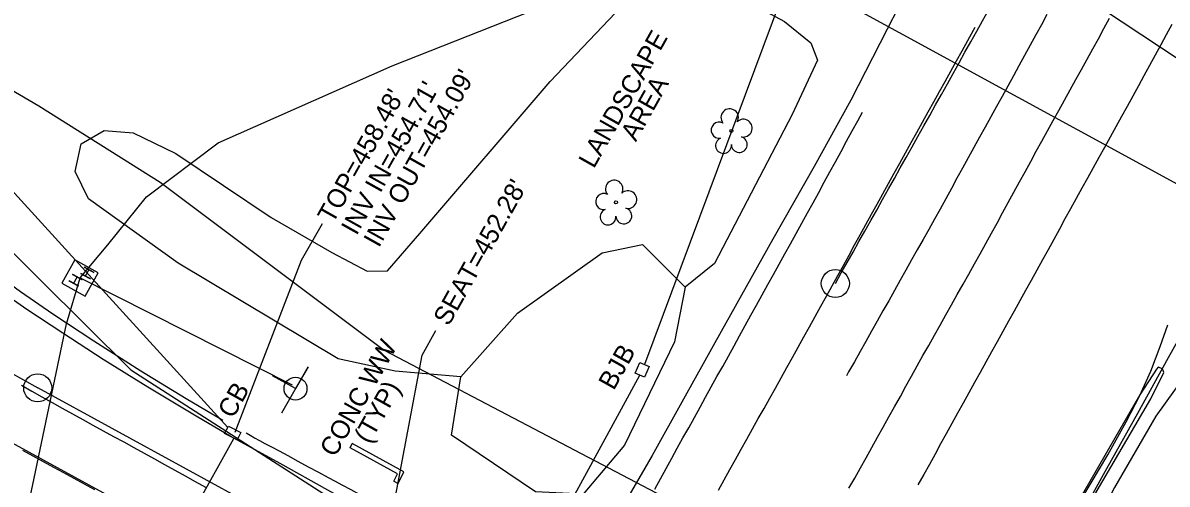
# Model space of a CAD drawing. Extents: x 2074109 to 2077820, y 741079 to 746031.
# Drawn here: x 2075369.9 to 2075614.7, y 743471.4 to 743570.1 of the extents above; entities that cross this region are included whole.
import ezdxf

# ---------------------------------------------------------------- set-up
doc = ezdxf.new("R2010")
doc.units = 0
for name, color, linetype in [('Exist Guardrail', 7, 'Continuous'), ('Exist Horizontal Alignment', 7, 'Continuous'), ('Exist Horizontal Alignment Point', 7, 'Continuous'), ('Exist Roads Curbs', 7, 'Continuous'), ('Exist Roads EOP', 7, 'Continuous'), ('Exist Roads EOT', 7, 'Continuous'), ('Exist Structure Major Bridge Seat Leader', 7, 'Continuous'), ('Exist Structure Major Bridge Seat Top Elevation', 7, 'Continuous'), ('Exist Structure Major Bridge WW Text', 7, 'Continuous'), ('Exist Structure Minor Catch Basin', 7, 'Continuous'), ('Exist Structure Minor Catch Basin Leader', 7, 'Continuous'), ('Exist Structure Minor Catch Basin Text', 7, 'Continuous'), ('Exist Structure Minor Catch Basin Top Elevation', 7, 'Continuous'), ('Exist Structure Minor Head and End Wall', 7, 'Continuous'), ('Exist Structure Minor Junction Box', 7, 'Continuous'), ('Exist Structure Minor Junction Box Text', 7, 'Continuous'), ('Exist Structure Minor Pipes RCP 15 Inch', 7, 'Continuous'), ('Exist Structure Minor Pipes RCP 15 Inch Invert', 7, 'Continuous'), ('Exist Structure Minor Pipes RCP 36 Inch', 7, 'Continuous'), ('Exist Utilities Gas UG Line SUE LOS B', 7, 'Continuous'), ('Exist Utilities Power Joint Use Telephone CELL', 7, 'Continuous'), ('Exist Utilities Power UG Cable SUE LOS B', 7, 'Continuous'), ('Exist Utilities Telephone UG Conduit SUE LOS B', 7, 'Continuous'), ('Exist Utilities Telephone UG FO SUE LOS B', 7, 'Continuous'), ('Exist Utilities TV Hand Hole CELL', 7, 'Continuous'), ('Exist Utilities Water UG Line SUE LOS B', 7, 'Continuous'), ('Exist Vegetation Hedge Row', 7, 'Continuous'), ('Exist Vegetation Hedge Row Text', 7, 'Continuous'), ('Exist Vegetation Tree CELL', 7, 'Continuous'), ('Exist Vegetation Woods Line', 7, 'Continuous')]:
    doc.layers.add(name, color=color, linetype=linetype)

msp = doc.modelspace()

# ---------------------------------------------------------------- linework, layer by layer
at = {"layer": 'Exist Guardrail'}
msp.add_line((2075608.81, 743490.52), (2075585.08, 743449.24), dxfattribs=at)
msp.add_lwpolyline([(2075566.68, 743406.83), (2075570.84, 743414.46), (2075580.6, 743432.36), (2075594.55, 743459.51), (2075599.18, 743469.22), (2075611.18, 743489.67), (2075614, 743495.32), (2075613.66, 743496.05), (2075612.79, 743496.46), (2075612.4, 743496.03), (2075608.81, 743490.52)], dxfattribs=at)
at = {"layer": 'Exist Horizontal Alignment'}
for p, q in [((2074769.18, 743807.11), (2075920.37, 743178.35)), ((2075444.78, 743452.87), (2075373.12, 743492))]:
    msp.add_line(p, q, dxfattribs=at)
for centre, radius, start, end in [((2065746.77, 748969.72), 11283.45, 330.581241, 339.398504), ((2065715.23, 749056.64), 11283.45, 330.581241, 331.000067), ((2075492.33, 743710.26), 248.69, 215.7386, 241.3572)]:
    msp.add_arc(centre, radius, start, end, dxfattribs=at)
at = {"layer": 'Exist Horizontal Alignment Point'}
for centre in [(2075543.71, 743514.33), (2075373.12, 743492)]:
    msp.add_circle(centre, 3, dxfattribs=at)
at = {"layer": 'Exist Roads Curbs'}
for points in [[(2075307.15, 743570.9), (2075310.12, 743567.26), (2075315.37, 743561.06), (2075321.1, 743554.42), (2075325.85, 743549.26), (2075330.36, 743544.77), (2075335.65, 743539.76), (2075345.03, 743531.53), (2075356.37, 743522.33), (2075363.48, 743516.95), (2075369.43, 743512.64), (2075376.35, 743507.87), (2075385.09, 743502.08), (2075395.18, 743495.66), (2075404.84, 743489.75), (2075412, 743485.54), (2075412.72, 743485.12)], [(2075417.69, 743482.38), (2075418.53, 743481.88), (2075419.49, 743481.34), (2075420.55, 743480.75), (2075421.73, 743480.12), (2075423.1, 743479.4), (2075424.73, 743478.52), (2075426.61, 743477.5), (2075428.76, 743476.34), (2075430.99, 743475.12), (2075433.14, 743473.96), (2075435.22, 743472.85), (2075436.72, 743472.05), (2075438.18, 743471.28), (2075440.06, 743470.26), (2075441.88, 743469.26), (2075443.64, 743468.26), (2075444.49, 743467.77)]]:
    msp.add_lwpolyline(points, dxfattribs=at)
at = {"layer": 'Exist Roads EOP'}
for points in [[(2075559.5, 743577.98), (2075554.8, 743568.73), (2075547.03, 743553.55), (2075539.18, 743539.38), (2075530.34, 743523.8), (2075517.96, 743501.62), (2075504.54, 743477.52), (2075492.04, 743456), (2075482.7, 743440.16), (2075465.16, 743408.97), (2075448.94, 743380.02), (2075438.36, 743361.14), (2075432.82, 743350.24), (2075423.13, 743332.91), (2075408.43, 743306.71), (2075394.81, 743282.87), (2075378.9, 743255.03), (2075364.05, 743228.71), (2075347.68, 743199.79), (2075332.2, 743172.4), (2075317.22, 743145.53), (2075301.28, 743116.93)], [(2075445.35, 743464.44), (2075424.96, 743475.81), (2075414.28, 743481.69), (2075407.34, 743485.74), (2075396.65, 743492.12), (2075387.15, 743498.07), (2075378.48, 743503.71), (2075370.8, 743508.8), (2075365.1, 743512.76), (2075359.72, 743516.76), (2075352.43, 743522.45), (2075343.87, 743529.41), (2075336.63, 743535.65), (2075330.1, 743541.75), (2075323.4, 743548.45), (2075316.7, 743555.85), (2075309.06, 743565.08), (2075302.29, 743573.79)], [(2075629.48, 743509.98), (2075612.24, 743485.93), (2075603.42, 743470.69), (2075597.29, 743458.57), (2075588.31, 743442.87), (2075576.16, 743421.96), (2075567.04, 743406.6), (2075558.96, 743392.83), (2075547.09, 743371), (2075533.33, 743345.7), (2075516.25, 743314.4), (2075505.25, 743295.15), (2075496.54, 743281.14), (2075486.37, 743264.69)], [(2075486.59, 743271.21), (2075492.62, 743282.79), (2075498.41, 743293.66), (2075503.35, 743303.11), (2075507.27, 743311), (2075512.55, 743321.1), (2075520.08, 743334.84), (2075528.48, 743350.15), (2075537.18, 743366.11), (2075545.57, 743381.57), (2075553.44, 743396.13), (2075561.87, 743411.12), (2075571.26, 743427.01), (2075580.6, 743442.44), (2075589.42, 743456.78), (2075596.67, 743468.69), (2075601.96, 743477.67), (2075605.92, 743484.73), (2075608.84, 743490.35), (2075611.2, 743495.58), (2075613.21, 743500.83), (2075614.86, 743505.48)]]:
    msp.add_lwpolyline(points, dxfattribs=at)
at = {"layer": 'Exist Roads EOT'}
for points in [[(2075588.98, 743571.9), (2075587.79, 743569.71), (2075586.59, 743567.51), (2075585.4, 743565.32), (2075584.2, 743563.12), (2075582.99, 743560.93), (2075581.79, 743558.74), (2075580.58, 743556.55), (2075579.38, 743554.36), (2075578.17, 743552.17), (2075576.97, 743549.98), (2075575.76, 743547.79), (2075574.55, 743545.61), (2075573.35, 743543.42), (2075572.14, 743541.23), (2075570.94, 743539.04), (2075569.73, 743536.85), (2075568.53, 743534.65), (2075567.33, 743532.46), (2075566.13, 743530.27), (2075564.92, 743528.08), (2075563.69, 743525.9), (2075562.47, 743523.72), (2075561.24, 743521.55), (2075560.02, 743519.37), (2075558.8, 743517.19), (2075557.57, 743515.01), (2075556.35, 743512.83), (2075555.13, 743510.65), (2075553.9, 743508.47), (2075552.68, 743506.29), (2075551.46, 743504.11), (2075550.23, 743501.93), (2075549, 743499.75), (2075547.78, 743497.57), (2075546.55, 743495.4), (2075546.09, 743494.58)], [(2075546.63, 743470.52), (2075547.85, 743472.7), (2075549.07, 743474.88), (2075550.29, 743477.06), (2075551.52, 743479.24), (2075552.74, 743481.43), (2075553.96, 743483.61), (2075555.18, 743485.79), (2075556.4, 743487.97), (2075557.62, 743490.15), (2075558.82, 743492.34), (2075560.03, 743494.53), (2075561.24, 743496.72), (2075562.46, 743498.9), (2075563.68, 743501.08), (2075564.91, 743503.26), (2075566.13, 743505.44), (2075567.35, 743507.62), (2075568.58, 743509.8), (2075569.8, 743511.98), (2075571.02, 743514.16), (2075572.25, 743516.34), (2075573.47, 743518.52), (2075574.69, 743520.7), (2075575.92, 743522.88), (2075577.12, 743525.07), (2075578.31, 743527.27), (2075579.49, 743529.47), (2075580.68, 743531.67), (2075581.88, 743533.86), (2075583.08, 743536.05), (2075584.29, 743538.24), (2075585.49, 743540.43), (2075586.7, 743542.62), (2075587.9, 743544.81), (2075589.11, 743547), (2075590.31, 743549.19), (2075591.51, 743551.38), (2075592.72, 743553.57), (2075593.92, 743555.76), (2075595.13, 743557.96), (2075596.34, 743560.14), (2075597.55, 743562.33), (2075598.77, 743564.51), (2075599.98, 743566.7), (2075601.16, 743568.9), (2075602.34, 743571.1)], [(2075518.73, 743470.13), (2075519.95, 743472.31), (2075521.16, 743474.5), (2075522.38, 743476.68), (2075523.6, 743478.86), (2075524.81, 743481.05), (2075526.03, 743483.23), (2075527.24, 743485.42), (2075528.46, 743487.6), (2075529.68, 743489.78), (2075530.89, 743491.97), (2075532.11, 743494.15), (2075533.32, 743496.34), (2075534.54, 743498.52), (2075535.76, 743500.7), (2075536.97, 743502.89), (2075538.19, 743505.07), (2075539.4, 743507.26), (2075540.6, 743509.45), (2075541.81, 743511.64), (2075543.02, 743513.83), (2075544.22, 743516.02), (2075545.43, 743518.21), (2075546.64, 743520.4), (2075547.84, 743522.58), (2075549.05, 743524.77), (2075550.26, 743526.96), (2075551.46, 743529.15), (2075552.67, 743531.34), (2075553.88, 743533.53), (2075555.08, 743535.72), (2075556.29, 743537.91), (2075557.5, 743540.1), (2075558.71, 743542.28), (2075559.92, 743544.47), (2075561.13, 743546.65), (2075562.35, 743548.84), (2075563.56, 743551.03), (2075564.77, 743553.21), (2075565.99, 743555.4), (2075567.2, 743557.58), (2075568.41, 743559.77), (2075569.63, 743561.95), (2075570.84, 743564.14), (2075572.05, 743566.32), (2075573.27, 743568.51), (2075573.62, 743569.15)], [(2075615.7, 743569.76), (2075614.5, 743567.57), (2075613.31, 743565.37), (2075612.11, 743563.18), (2075610.92, 743560.98), (2075609.72, 743558.78), (2075608.52, 743556.59), (2075607.32, 743554.4), (2075606.11, 743552.21), (2075604.9, 743550.03), (2075603.7, 743547.84), (2075602.49, 743545.65), (2075601.28, 743543.46), (2075600.07, 743541.27), (2075598.87, 743539.08), (2075597.66, 743536.89), (2075596.45, 743534.7), (2075595.25, 743532.51), (2075594.04, 743530.32), (2075592.83, 743528.14), (2075591.63, 743525.95), (2075590.42, 743523.76), (2075589.21, 743521.57), (2075588, 743519.38), (2075586.8, 743517.19), (2075585.59, 743515), (2075584.38, 743512.81), (2075583.18, 743510.62), (2075581.97, 743508.44), (2075580.76, 743506.25), (2075579.55, 743504.06), (2075578.34, 743501.87), (2075577.13, 743499.69), (2075575.92, 743497.5), (2075574.71, 743495.31), (2075573.5, 743493.12), (2075572.29, 743490.94), (2075571.08, 743488.75), (2075569.87, 743486.56), (2075568.66, 743484.37), (2075567.45, 743482.19), (2075566.24, 743480), (2075565.03, 743477.81), (2075563.82, 743475.62), (2075562.61, 743473.44), (2075561.39, 743471.25)], [(2075505.08, 743470.36), (2075506.29, 743472.55), (2075507.5, 743474.74), (2075508.71, 743476.93), (2075509.92, 743479.11), (2075511.13, 743481.3), (2075512.35, 743483.48), (2075513.56, 743485.67), (2075514.77, 743487.86), (2075515.98, 743490.04), (2075517.19, 743492.23), (2075518.4, 743494.42), (2075519.62, 743496.6), (2075520.83, 743498.79), (2075522.04, 743500.98), (2075523.25, 743503.16), (2075524.46, 743505.35), (2075525.67, 743507.54), (2075526.88, 743509.72), (2075528.09, 743511.91), (2075529.3, 743514.1), (2075530.51, 743516.28), (2075531.73, 743518.47), (2075532.94, 743520.66), (2075534.15, 743522.84), (2075535.36, 743525.03), (2075536.56, 743527.22), (2075537.76, 743529.42), (2075538.95, 743531.61), (2075540.15, 743533.81), (2075541.34, 743536), (2075542.54, 743538.2), (2075543.73, 743540.39), (2075544.93, 743542.59), (2075546.12, 743544.78), (2075547.32, 743546.98), (2075548.51, 743549.17), (2075549.51, 743551)], [(2075369.65, 743492.55), (2075371.83, 743491.33), (2075374.01, 743490.11), (2075376.19, 743488.9), (2075378.38, 743487.69), (2075380.57, 743486.47), (2075382.75, 743485.26), (2075384.94, 743484.05), (2075387.13, 743482.84), (2075389.32, 743481.63), (2075391.51, 743480.42), (2075393.69, 743479.21), (2075395.88, 743478.01), (2075398.07, 743476.8), (2075400.26, 743475.59), (2075402.45, 743474.38), (2075404.63, 743473.17), (2075406.82, 743471.96), (2075409.01, 743470.75)], [(2075369.9, 743478.68), (2075372.09, 743477.48), (2075374.28, 743476.27), (2075376.47, 743475.06), (2075378.66, 743473.86), (2075380.86, 743472.66), (2075383.05, 743471.46), (2075385.24, 743470.27)]]:
    msp.add_lwpolyline(points, dxfattribs=at)
at = {"layer": 'Exist Structure Major Bridge Seat Leader'}
msp.add_lwpolyline([(2075449.18, 743466.47), (2075455.35, 743499.03), (2075458.28, 743504.27)], dxfattribs=at)
at = {"layer": 'Exist Structure Minor Catch Basin'}
msp.add_lwpolyline([(2075413.89, 743483.84), (2075416.59, 743482.46), (2075415.78, 743480.87), (2075413.08, 743482.25)], close=True, dxfattribs=at)
at = {"layer": 'Exist Structure Minor Catch Basin Leader'}
msp.add_lwpolyline([(2075415.33, 743482.54), (2075429.57, 743519.34), (2075434, 743527.2)], dxfattribs=at)
at = {"layer": 'Exist Structure Minor Head and End Wall'}
for points in [[(2075449.29, 743472.02), (2075450.1, 743473.63), (2075439.92, 743479.2), (2075440.4, 743480.08)], [(2075449.29, 743472.02), (2075450.18, 743471.57), (2075451.43, 743474.04), (2075440.4, 743480.08)]]:
    msp.add_lwpolyline(points, dxfattribs=at)
at = {"layer": 'Exist Structure Minor Junction Box'}
msp.add_lwpolyline([(2075500.9, 743495.15), (2075501.87, 743497.44), (2075503.9, 743496.58), (2075502.93, 743494.29)], close=True, dxfattribs=at)
at = {"layer": 'Exist Structure Minor Pipes RCP 15 Inch'}
for p, q in [((2075413.76, 743483.52), (2075273.44, 743637.59)), ((2075372.17, 743404.16), (2075415.09, 743481.19))]:
    msp.add_line(p, q, dxfattribs=at)
at = {"layer": 'Exist Structure Minor Pipes RCP 36 Inch'}
for p, q in [((2075597.45, 743750.35), (2075502.89, 743497.01)), ((2075364.8, 743242.78), (2075501.91, 743494.72))]:
    msp.add_line(p, q, dxfattribs=at)
at = {"layer": 'Exist Utilities Gas UG Line SUE LOS B'}
msp.add_lwpolyline([(2075544.69, 743574.93), (2075774.64, 743449.58), (2075786.68, 743440.92), (2075834.72, 743415.6), (2075897.9, 743381.57), (2075936.93, 743360.69), (2075971.28, 743343.48), (2075996.08, 743328.1)], dxfattribs=at)
at = {"layer": 'Exist Utilities Power Joint Use Telephone CELL'}
msp.add_line((2075428.27, 743491.84), (2075428.27, 743491.84), dxfattribs=at)
msp.add_lwpolyline([(2075425.36, 743486.66), (2075430.94, 743496.53), (2075428.28, 743491.83), (2075423.36, 743494.59)], dxfattribs=at)
msp.add_circle((2075428.26, 743491.85), 2.45, dxfattribs=at)
at = {"layer": 'Exist Utilities Power UG Cable SUE LOS B'}
msp.add_lwpolyline([(2075533.27, 743615.97), (2075567.2, 743595.41), (2075714.24, 743498.15), (2075756.41, 743472.15), (2075744.73, 743436.84), (2075735.98, 743400.81), (2075736.7, 743379.57), (2075744.38, 743367.05), (2075761.28, 743352.67), (2075771.54, 743346.58), (2075788.66, 743330.79), (2075794.6, 743320.93)], dxfattribs=at)
at = {"layer": 'Exist Utilities Telephone UG Conduit SUE LOS B'}
msp.add_lwpolyline([(2074852.23, 743796.93), (2074858.98, 743788.14), (2074871.16, 743780.09), (2074884.61, 743773.35), (2074910.14, 743759.3), (2074929.12, 743745.39), (2074958.42, 743728.87), (2074997.61, 743706.69), (2075052.29, 743677.02), (2075084.82, 743660.77), (2075107.9, 743645.87), (2075165.73, 743622.21), (2075198.81, 743604.97), (2075246.84, 743581.99), (2075289.9, 743561.06), (2075322.06, 743548.08), (2075339.73, 743539.52), (2075355.79, 743530.19), (2075360.13, 743528.64), (2075373.71, 743515.02), (2075393.05, 743495.87), (2075443.09, 743463.69), (2075672.89, 743341.39)], dxfattribs=at)
at = {"layer": 'Exist Utilities Telephone UG FO SUE LOS B'}
msp.add_line((2075382.17, 743515.51), (2075427.52, 743492.66), dxfattribs=at)
msp.add_lwpolyline([(2075222.87, 743080.84), (2075256.4, 743137.17), (2075288.87, 743193.63), (2075300.42, 743220.4), (2075312.11, 743252.93), (2075313.41, 743275.26), (2075321.97, 743323.29), (2075330.4, 743351.2), (2075353.35, 743389.78), (2075353.46, 743389.59), (2075359.52, 743410.61), (2075366.87, 743449.87), (2075369.9, 743460.77), (2075379.26, 743505.72), (2075382.17, 743515.51), (2075388.11, 743522.63), (2075396.38, 743532.84), (2075411.7, 743544.41), (2075448.92, 743560.88), (2075483.77, 743574.68)], dxfattribs=at)
at = {"layer": 'Exist Utilities TV Hand Hole CELL'}
msp.add_line((2075382.17, 743515.51), (2075382.17, 743515.51), dxfattribs=at)
msp.add_lwpolyline([(2075383.3, 743511.61), (2075386.08, 743516.64), (2075381.05, 743519.42), (2075378.27, 743514.39), (2075383.3, 743511.61)], dxfattribs=at)
at = {"layer": 'Exist Utilities Water UG Line SUE LOS B'}
msp.add_lwpolyline([(2074661.41, 743894.07), (2074669.03, 743889.86), (2074695.78, 743877.33), (2074733.5, 743856.32), (2074766.19, 743837.03), (2074806.52, 743814.12), (2074828.36, 743801.4), (2074869.77, 743778.77), (2075138.71, 743653.82), (2075174.59, 743638.37), (2075261.38, 743603.22), (2075296.53, 743589.33), (2075345.56, 743568.62), (2075373.37, 743552.36), (2075399.34, 743536.02), (2075447.19, 743500.05), (2075713.36, 743360.43), (2075744.72, 743342.27), (2075764.85, 743330.17), (2075782.75, 743317.7), (2075822.78, 743289.56)], dxfattribs=at)
at = {"layer": 'Exist Vegetation Hedge Row'}
for points in [[(2075402.68, 743542.14), (2075423.02, 743528.44), (2075436.01, 743520.98), (2075443.55, 743516.96), (2075447.92, 743517.04), (2075454.88, 743525.04), (2075482.7, 743557.52), (2075500.81, 743576.63), (2075507.91, 743582.11), (2075515.67, 743579.69), (2075532.87, 743570.38), (2075538.46, 743565.8), (2075539.89, 743562.14), (2075534.48, 743550.51), (2075517.86, 743518.61), (2075511.56, 743513.56)], [(2075463.64, 743494.33), (2075449.57, 743495.58), (2075437.41, 743498.18), (2075403.15, 743518.65), (2075384, 743532.48), (2075381.12, 743538.31), (2075382.44, 743544.23), (2075387.33, 743547.04), (2075393.52, 743546.56), (2075402.68, 743542.14)]]:
    msp.add_lwpolyline(points, dxfattribs=at)
at = {"layer": 'Exist Vegetation Tree CELL'}
for p, q in [((2075521.49, 743546.98), (2075521.49, 743546.98)), ((2075496.8, 743531.69), (2075496.8, 743531.69))]:
    msp.add_line(p, q, dxfattribs=at)
for centre in [(2075521.49, 743546.98), (2075496.8, 743531.69)]:
    msp.add_circle(centre, 0.326, dxfattribs=at)
for centre, radius, start, end in [((2075521.11, 743549.85), 1.86, 330.1651, 219.7134), ((2075518.89, 743547.13), 1.73, 62.6636, 279.3457), ((2075524.04, 743547.57), 1.9, 257.1011, 134.1999), ((2075519.79, 743543.86), 1.69, 111.5671, 6.231), ((2075523.17, 743544.08), 1.7, 181.2822, 74.56), ((2075496.42, 743534.57), 1.86, 330.1651, 219.7134), ((2075499.35, 743532.28), 1.9, 257.1011, 134.1999), ((2075494.2, 743531.85), 1.73, 62.6636, 279.3457), ((2075495.1, 743528.57), 1.69, 111.5671, 6.231), ((2075498.48, 743528.79), 1.7, 181.2822, 74.56)]:
    msp.add_arc(centre, radius, start, end, dxfattribs=at)
at = {"layer": 'Exist Vegetation Woods Line'}
msp.add_lwpolyline([(2075502.44, 743522.66), (2075511.56, 743513.56), (2075509.29, 743501.87), (2075498.6, 743479.74), (2075489.8, 743469.25), (2075479.55, 743469.73), (2075461.61, 743481.91), (2075463.64, 743494.33), (2075475.73, 743508), (2075493.85, 743520.91), (2075502.44, 743522.66)], dxfattribs=at)

# ---------------------------------------------------------------- texts
at = {"layer": 'Exist Structure Major Bridge Seat Top Elevation'}
msp.add_text("SEAT=452.28'", height=4, rotation=60.742, dxfattribs=at).set_placement((2075461.01, 743505.03))
at = {"layer": 'Exist Structure Major Bridge WW Text'}
for s, p in [('CONC WW ', (2075436.72, 743476.97)), ('(TYP)', (2075444.06, 743479.83))]:
    msp.add_text(s, height=4, rotation=60.7411, dxfattribs=at).set_placement(p)
at = {"layer": 'Exist Structure Minor Catch Basin Text'}
msp.add_text('CB', height=4, rotation=60.742, dxfattribs=at).set_placement((2075414.9, 743485.24))
at = {"layer": 'Exist Structure Minor Catch Basin Top Elevation'}
msp.add_text("TOP=458.48'", height=4, rotation=60.7028, dxfattribs=at).set_placement((2075436.24, 743526.96))
at = {"layer": 'Exist Structure Minor Junction Box Text'}
msp.add_text('BJB', height=4, rotation=60.7411, dxfattribs=at).set_placement((2075496.32, 743491.29))
at = {"layer": 'Exist Structure Minor Pipes RCP 15 Inch Invert'}
for s, p in [("INV OUT=454.09'", (2075446.09, 743521.83)), ("INV IN=454.71'", (2075441.3, 743524.44))]:
    msp.add_text(s, height=4, rotation=60.7028, dxfattribs=at).set_placement(p)
at = {"layer": 'Exist Utilities TV Hand Hole CELL'}
for p in [(2075384.25, 743514.92), (2075381.73, 743513.37)]:
    msp.add_text('H', height=2.5, rotation=61.1016, dxfattribs=at).set_placement(p)
at = {"layer": 'Exist Vegetation Hedge Row Text'}
for s, p in [('LANDSCAPE ', (2075492.07, 743538.75)), ('AREA', (2075501.06, 743544.51))]:
    msp.add_text(s, height=4, rotation=60.5812, dxfattribs=at).set_placement(p)

doc.saveas('drawing.dxf')
